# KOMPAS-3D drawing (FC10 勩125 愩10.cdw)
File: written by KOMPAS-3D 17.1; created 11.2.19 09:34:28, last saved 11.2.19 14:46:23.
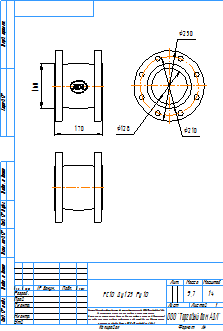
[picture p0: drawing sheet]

Sheet 1: A4, portrait

Title block, sheet 1: name: FC10 Ду125 Ру10; mass: 9,7; sheets: 1; sheet format: A4; stored path: \\adlc.lan\data\АДЛ_ПКД\3D-модели\ADL production\Гибкие вставки серии FC\FC10\KOMPAS 2D\FC10 Ду125 Ру10.cdw

Views: Вид 1
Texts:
  kka
  adl
  Рама для чертежей
  Лит-Масса-Масштаб
  Материал-Предприятие
  Масштаб
  Изм.
  Лист
  № докум.
  Подп.
  Дата
  Лит.
  Разраб.
  Пров.
  Т.контр.
  Листов
  Внимание! Данный продукт является объектом авторского права ООО «Торговый Дом АДЛ».
  Запрещается изменение, копирование, распространение
  (в том числе путем копирования на другие сайты и ресурсы в Интернете)
  или любое иное использование информации и объектов без предварительного
  согласия правообладателя (ООО «Торговый Дом АДЛ»).
  Н.контр.
  Утв.
  ООО "Торговый дом АДЛ"
  Изменение
  Номер документа
  Подпись
  Обозначение документа
  Наименование изделия
  Масса изделия по ГОСТ 2.109-73
  Порядковый номер листа
  Общее количество листов в документе
  Характер работы, выполненной лицом, подписавшим документ
  Наименование или индекс предприятия, выпускающего документ
  Инв. № подл.
  Подп. и дата
  Взам. инв. №
  Инв. № дубл.
  Инвентарный номер подлинника по ГОСТ 2.501-68
  Подпись принявшего подлинник в отдел технической документации
  Инвентарный номер подлинника, взамен которого выпущен данный подлинник
  Инвентарный номер дубликата по ГОСТ 2.502-68
  Подпись принявшего дубликат в отдел технической документации
  Справ. №
  Перв. примен.
  Обозначение документа, взамен или на основании которого выпущен данный документ
  Обозначение документа, в котором впервые записан данный документ
  Подпись лица, копировавшего чертеж
  Обозначение формата листа
  !Рама для чертежа
Dimensions and other numbers on the sheet: 170; 160; 128; 250; 210; 1:4; 1; 9,7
